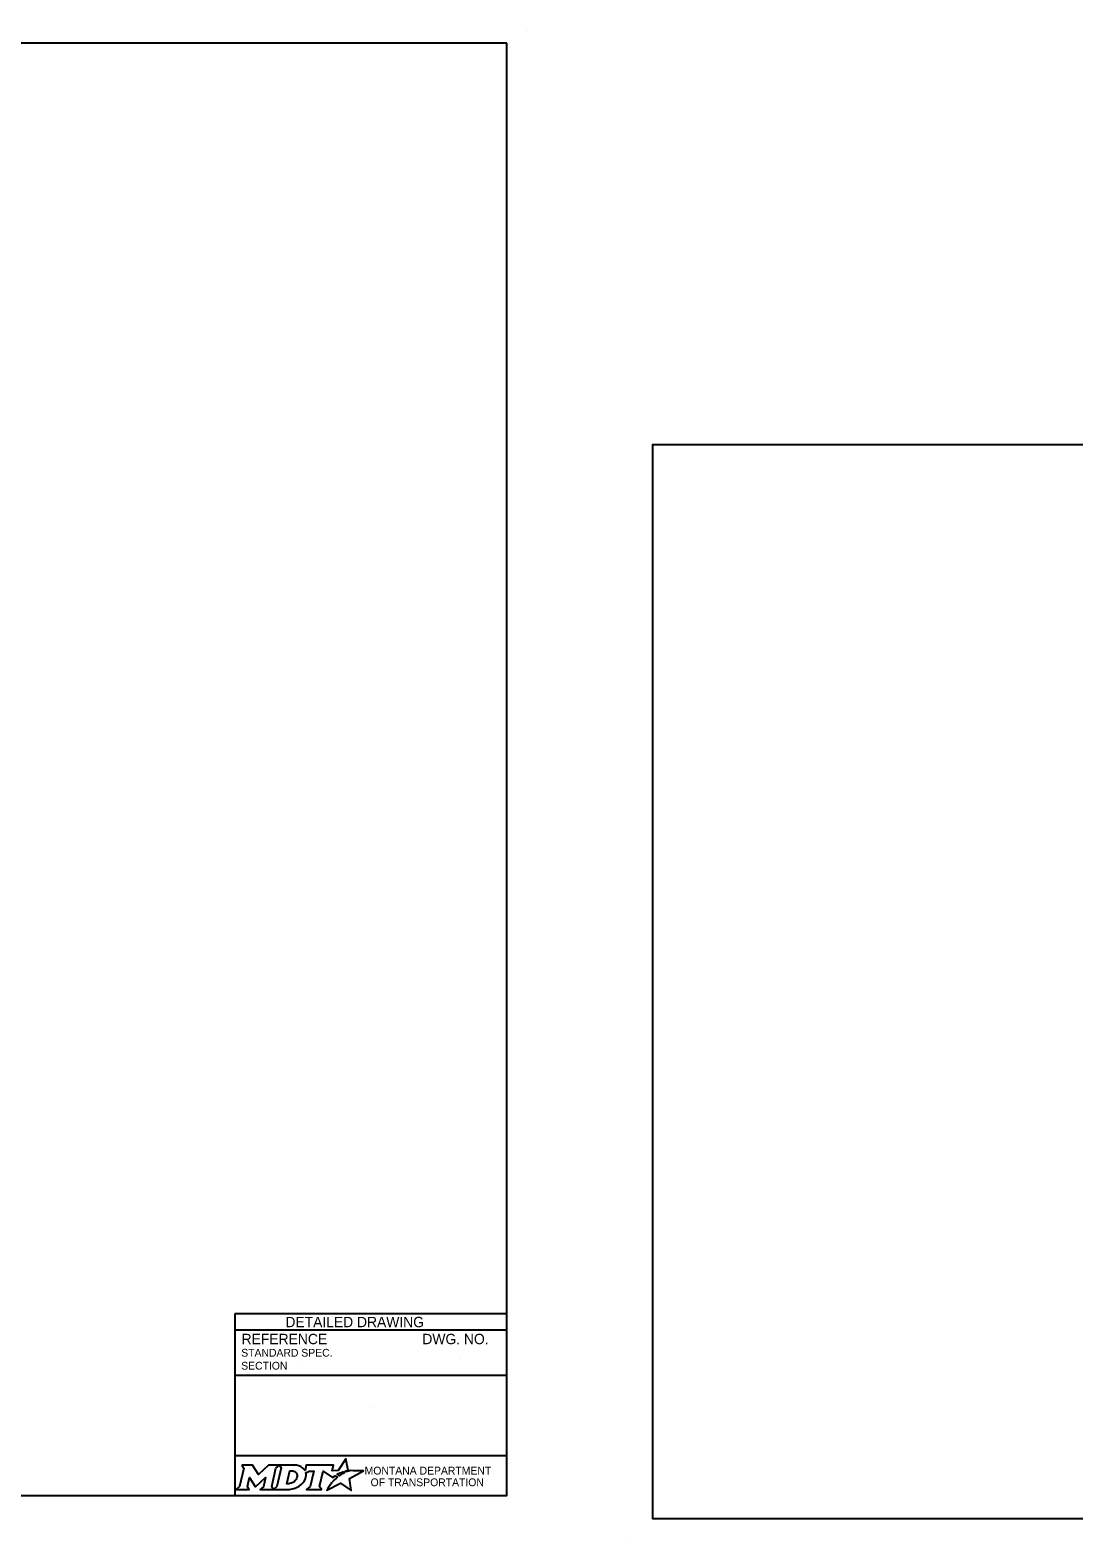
# Model space of a CAD drawing. Extents: x 49991.4 to 50021, y 49987.6 to 50011.4.
# Drawn here: x 50004.94 to 50012.99, y 49999.74 to 50011.36 of the extents above; entities that cross this region are included whole.
import ezdxf

# ---------------------------------------------------------------- set-up
doc = ezdxf.new("R2010")
doc.units = 0
doc.layers.add('Level 1', color=7, linetype='Continuous')
doc.layers.add('Level 2', color=7, linetype='Continuous')

msp = doc.modelspace()

# ---------------------------------------------------------------- linework, layer by layer
at = {"layer": 'Level 1'}
for p, q in [((50008.765, 50011.363), (50008.765, 50011.363)), ((50009.537, 49999.736), (50009.537, 49999.736))]:
    msp.add_line(p, q, dxfattribs=at)
for points in [[(50008.615, 50011.263), (50000.336, 50011.263), (50000.336, 50000.062), (50008.615, 50000.062)], [(50020.938, 50008.165), (50009.737, 50008.165), (50009.737, 49999.886), (50020.938, 49999.886)]]:
    msp.add_lwpolyline(points, close=True, dxfattribs=at)
at = {"layer": 'Level 2'}
for p, q in [((50008.615, 50001.462), (50006.515, 50001.462)), ((50006.515, 50001.462), (50006.515, 50000.062)), ((50008.615, 50001.337), (50006.515, 50001.337)), ((50007.009, 50001.063), (50007.009, 50001.063)), ((50008.251, 50001.122), (50008.251, 50001.122)), ((50008.615, 50000.987), (50006.515, 50000.987)), ((50007.565, 50000.738), (50007.565, 50000.738)), ((50008.615, 50000.369), (50006.515, 50000.369))]:
    msp.add_line(p, q, dxfattribs=at)
for points in [[(50007.377, 50000.245), (50007.367, 50000.25), (50007.378, 50000.253), (50007.39, 50000.255), (50007.373, 50000.345), (50007.313, 50000.254), (50007.266, 50000.253), (50007.276, 50000.297), (50007.067, 50000.297), (50007.057, 50000.255), (50007.051, 50000.263)], [(50006.57, 50000.297), (50006.584, 50000.274), (50006.551, 50000.131), (50006.525, 50000.108), (50006.627, 50000.108), (50006.613, 50000.131), (50006.629, 50000.201), (50006.673, 50000.132), (50006.678, 50000.132), (50006.753, 50000.202), (50006.737, 50000.13), (50006.712, 50000.108), (50006.814, 50000.108), (50006.8, 50000.132), (50006.833, 50000.274)], [(50006.833, 50000.274), (50006.859, 50000.297), (50006.776, 50000.297), (50006.697, 50000.224), (50006.652, 50000.297), (50006.57, 50000.297)], [(50006.972, 50000.297), (50006.859, 50000.297), (50006.873, 50000.275), (50006.839, 50000.131), (50006.814, 50000.108), (50006.925, 50000.108)], [(50006.996, 50000.211), (50006.995, 50000.203), (50006.992, 50000.193), (50006.988, 50000.185), (50006.982, 50000.178), (50006.976, 50000.171), (50006.968, 50000.164), (50006.959, 50000.16), (50006.95, 50000.156), (50006.941, 50000.154), (50006.932, 50000.153), (50006.916, 50000.153), (50006.94, 50000.253), (50006.956, 50000.253), (50006.963, 50000.252), (50006.971, 50000.25), (50006.977, 50000.247), (50006.983, 50000.243), (50006.988, 50000.238), (50006.992, 50000.232), (50006.995, 50000.226), (50006.996, 50000.218), (50006.996, 50000.215), (50006.996, 50000.211)], [(50007.064, 50000.238), (50007.088, 50000.251), (50007.125, 50000.251), (50007.097, 50000.131), (50007.069, 50000.108), (50007.185, 50000.108), (50007.168, 50000.131), (50007.196, 50000.251), (50007.268, 50000.2), (50007.289, 50000.215), (50007.309, 50000.204)], [(50007.253, 50000.148), (50007.237, 50000.124), (50007.233, 50000.116), (50007.227, 50000.107), (50007.225, 50000.103), (50007.33, 50000.156), (50007.414, 50000.101), (50007.401, 50000.194), (50007.508, 50000.252), (50007.458, 50000.253), (50007.428, 50000.253), (50007.407, 50000.254), (50007.401, 50000.252), (50007.396, 50000.251), (50007.387, 50000.249), (50007.377, 50000.245)], [(50007.327, 50000.217), (50007.324, 50000.215), (50007.306, 50000.225), (50007.316, 50000.231), (50007.32, 50000.233), (50007.329, 50000.237), (50007.335, 50000.239), (50007.343, 50000.243), (50007.35, 50000.245), (50007.362, 50000.238), (50007.358, 50000.236), (50007.353, 50000.233), (50007.349, 50000.231), (50007.344, 50000.228), (50007.342, 50000.227), (50007.339, 50000.225), (50007.337, 50000.224), (50007.334, 50000.222), (50007.332, 50000.221), (50007.329, 50000.219), (50007.327, 50000.217)], [(50006.97, 50000.116), (50006.979, 50000.118), (50006.992, 50000.124), (50007.012, 50000.135)], [(50007.267, 50000.164), (50007.267, 50000.164)]]:
    msp.add_lwpolyline(points, dxfattribs=at)
for centre, radius, start, end in [((50006.995, 50000.219), 0.0709, 339.5329, 15.8582), ((50006.951, 50000.236), 0.118, 300.9103, 339.1383)]:
    msp.add_arc(centre, radius, start, end, dxfattribs=at)
for centre, major_axis, ratio, start_param, end_param in [((50006.97, 50000.25), (0.0834, -0.0037), 0.568097, 0.61298, 1.570796), ((50007.026, 50000.257), (0.0361, -0.0295), 0.469099, 1.225588, 1.570796), ((50006.925, 50000.257), (0, 0.148), 0.987302, 3.139398, 3.456847), ((50007.26, 50000.156), (-0.00694, -0.00806), 0.008222, 0, 3.137361), ((50007.276, 50000.174), (-0.0098, -0.0102), 0.016458, 3.141593, 6.279097), ((50007.297, 50000.194), (-0.0112, -0.0097), 0.021651, 3.157348, 6.283185)]:
    msp.add_ellipse(centre, major_axis=major_axis, ratio=ratio, start_param=start_param, end_param=end_param, dxfattribs=at)

# ---------------------------------------------------------------- texts
for s, height, p in [('DETAILED DRAWING', 0.0799, (50006.906, 50001.36)), ('REFERENCE', 0.08, (50006.568, 50001.229)), ('DWG. NO.', 0.08, (50007.962, 50001.229)), ('STANDARD SPEC.', 0.06, (50006.565, 50001.133)), ('SECTION', 0.06, (50006.565, 50001.033))]:
    msp.add_text(s, height=height, dxfattribs=at).set_placement(p)
for s, p in [('MONTANA DEPARTMENT', (50007.517, 50000.224)), ('OF TRANSPORTATION', (50007.563, 50000.134))]:
    msp.add_text(s, height=0.06, rotation=360, dxfattribs=at).set_placement(p)

doc.saveas('drawing.dxf')
